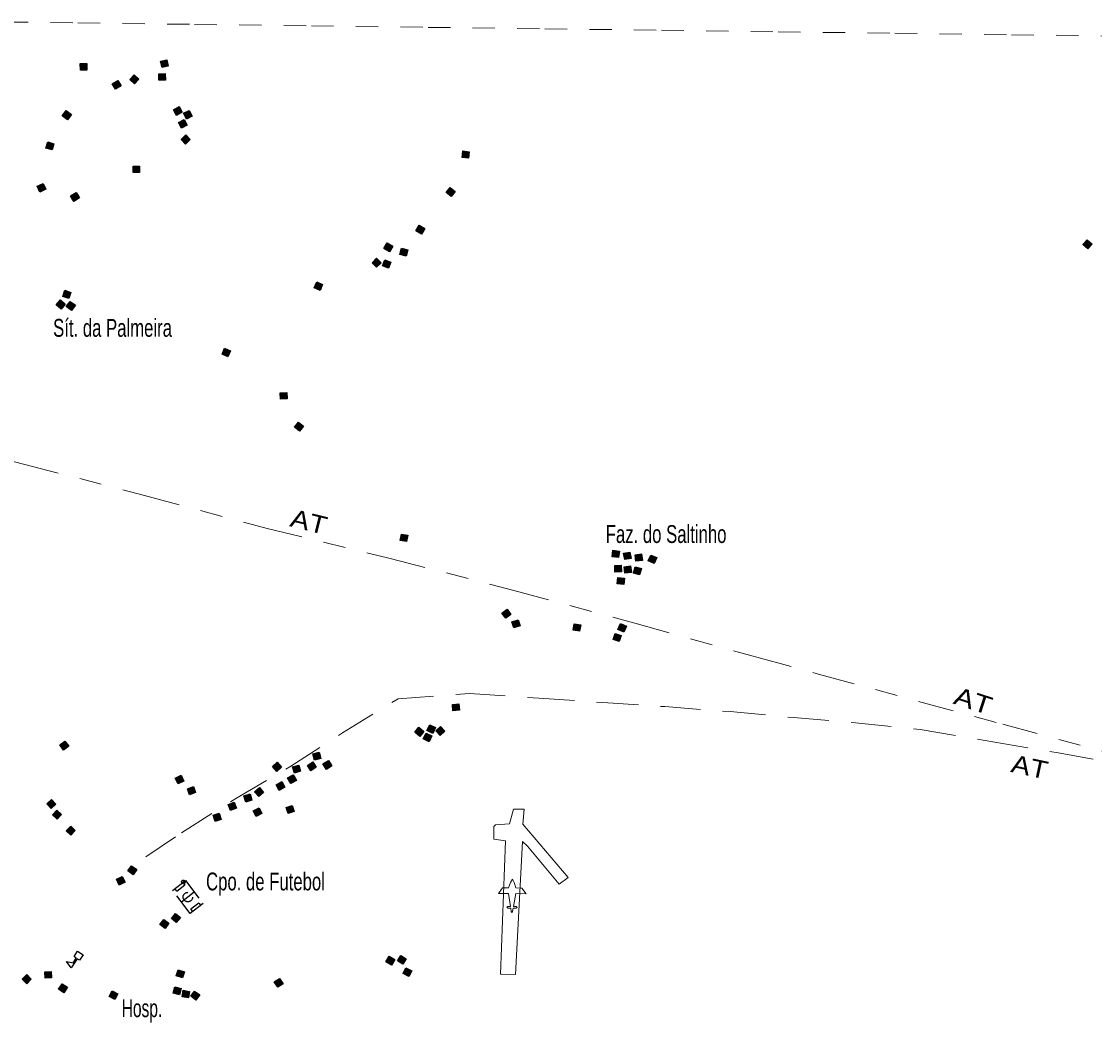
# Model space of a CAD drawing. Extents: x 679 to 705, y 7427.4 to 7455.4.
# Drawn here: x 688.008 to 692.818, y 7450.789 to 7455.274 of the extents above; entities that cross this region are included whole.
import ezdxf
from ezdxf.enums import TextEntityAlignment as Align

# ---------------------------------------------------------------- set-up
doc = ezdxf.new("R2010")
doc.units = 0
doc.header["$LTSCALE"] = 0.032
doc.header["$PDMODE"] = 32
doc.header["$PDSIZE"] = 0.016
for name, pattern in [('DOT_DASHED', [7.7, 5, -1.2, 0.3, -1.2]), ('MEDIUM_DASHED', [4.5, 3, -1.5]), ('SHORT_DASHED', [2.7, 1.5, -1.2])]:
    doc.linetypes.add(name, pattern=pattern)
for name, color, linetype, lineweight in [('14', 7, 'MEDIUM_DASHED', 25), ('18', 7, 'Continuous', 13), ('2', 7, 'Continuous', 25), ('4', 7, 'Continuous', 25), ('56', 7, 'DOT_DASHED', 13), ('58', 7, 'SHORT_DASHED', 13)]:
    doc.layers.add(name, color=color, linetype=linetype, lineweight=lineweight)
doc.layers.add('61', color=7, linetype='Continuous')

msp = doc.modelspace()

# ---------------------------------------------------------------- hatches: boundary and pattern name
at = {"layer": '2'}
for points in [[(688.3013, 7455.0856), (688.3019, 7455.0566), (688.2729, 7455.0561), (688.2723, 7455.0851)], [(688.6602, 7455.1025), (688.6668, 7455.0742), (688.6385, 7455.0677), (688.632, 7455.0959)], [(688.5131, 7455.0352), (688.5347, 7455.0158), (688.5153, 7454.9943), (688.4937, 7455.0137)], [(688.6532, 7455.0403), (688.6537, 7455.0113), (688.6247, 7455.0108), (688.6242, 7455.0398)], [(688.4407, 7455.01), (688.4556, 7454.9852), (688.4307, 7454.9703), (688.4158, 7454.9951)], [(688.7148, 7454.8926), (688.7291, 7454.8674), (688.7038, 7454.8531), (688.6895, 7454.8783)], [(688.2092, 7454.8745), (688.2322, 7454.8568), (688.2145, 7454.8338), (688.1915, 7454.8515)], [(688.7607, 7454.8759), (688.7741, 7454.8502), (688.7484, 7454.8368), (688.735, 7454.8625)], [(688.7379, 7454.8348), (688.7515, 7454.8093), (688.726, 7454.7956), (688.7123, 7454.8211)], [(688.745, 7454.7656), (688.765, 7454.7446), (688.7441, 7454.7246), (688.724, 7454.7455)], [(688.126, 7454.7341), (688.154, 7454.7264), (688.1464, 7454.6984), (688.1184, 7454.7061)], [(690.0152, 7454.6906), (690.0121, 7454.6618), (689.9832, 7454.6649), (689.9864, 7454.6938)], [(688.5382, 7454.6263), (688.5382, 7454.5973), (688.5092, 7454.5973), (688.5092, 7454.6263)], [(688.1052, 7454.5483), (688.1174, 7454.522), (688.0912, 7454.5098), (688.0789, 7454.5361)], [(688.2531, 7454.5078), (688.2685, 7454.4832), (688.2439, 7454.4678), (688.2285, 7454.4924)], [(689.9301, 7454.5307), (689.9526, 7454.5125), (689.9344, 7454.4899), (689.9118, 7454.5082)], [(689.7918, 7454.3614), (689.8165, 7454.3463), (689.8014, 7454.3216), (689.7767, 7454.3367)], [(689.6334, 7454.2569), (689.6477, 7454.2821), (689.6729, 7454.2677), (689.6585, 7454.2426)], [(692.7855, 7454.296), (692.8074, 7454.277), (692.7884, 7454.2551), (692.7665, 7454.2741)], [(689.6003, 7454.2138), (689.6208, 7454.1932), (689.6003, 7454.1727), (689.5798, 7454.1933)], [(689.7114, 7454.258), (689.7397, 7454.2515), (689.7331, 7454.2232), (689.7049, 7454.2298)], [(689.6377, 7454.2058), (689.6648, 7454.1954), (689.6543, 7454.1683), (689.6273, 7454.1787)], [(688.2029, 7454.0697), (688.2302, 7454.0601), (688.2207, 7454.0327), (688.1933, 7454.0423)], [(689.3317, 7454.1072), (689.3584, 7454.096), (689.3472, 7454.0692), (689.3204, 7454.0805)], [(688.1828, 7454.0263), (688.205, 7454.0077), (688.1865, 7453.9855), (688.1642, 7454.004)], [(688.2273, 7454.02), (688.2502, 7454.0023), (688.2326, 7453.9794), (688.2096, 7453.9971)], [(688.9458, 7453.798), (688.9339, 7453.7716), (688.9075, 7453.7834), (688.9193, 7453.8099)], [(689.1977, 7453.6119), (689.1992, 7453.5829), (689.1702, 7453.5815), (689.1688, 7453.6104)], [(689.2504, 7453.4786), (689.2731, 7453.4606), (689.255, 7453.4379), (689.2323, 7453.4559)], [(689.7399, 7452.9719), (689.7344, 7452.9435), (689.7059, 7452.949), (689.7115, 7452.9775)], [(690.6886, 7452.9012), (690.685, 7452.8724), (690.6562, 7452.876), (690.6598, 7452.9048)], [(690.7355, 7452.897), (690.741, 7452.8685), (690.7125, 7452.8631), (690.707, 7452.8916)], [(690.7878, 7452.8882), (690.7918, 7452.8595), (690.763, 7452.8555), (690.7591, 7452.8842)], [(690.856, 7452.8717), (690.8444, 7452.8451), (690.8178, 7452.8567), (690.8294, 7452.8833)], [(690.6966, 7452.8377), (690.6979, 7452.8087), (690.6689, 7452.8074), (690.6676, 7452.8364)], [(690.7385, 7452.8346), (690.7423, 7452.8059), (690.7136, 7452.802), (690.7097, 7452.8308)], [(690.787, 7452.8225), (690.7789, 7452.7946), (690.7511, 7452.8027), (690.7591, 7452.8306)], [(690.7109, 7452.7801), (690.708, 7452.7513), (690.6792, 7452.7541), (690.682, 7452.7829)], [(690.1856, 7452.6404), (690.2026, 7452.6168), (690.1791, 7452.5999), (690.1621, 7452.6234)], [(690.2345, 7452.5933), (690.2435, 7452.5657), (690.216, 7452.5567), (690.207, 7452.5843)], [(690.5152, 7452.5712), (690.5105, 7452.5426), (690.4819, 7452.5473), (690.4866, 7452.5759)], [(690.6968, 7452.5233), (690.6877, 7452.4958), (690.6601, 7452.5049), (690.6693, 7452.5325)], [(690.72, 7452.5653), (690.7089, 7452.5385), (690.6821, 7452.5496), (690.6933, 7452.5764)], [(689.9686, 7452.2164), (689.9713, 7452.1876), (689.9424, 7452.1849), (689.9398, 7452.2138)], [(689.7899, 7452.1115), (689.8121, 7452.0929), (689.7934, 7452.0707), (689.7713, 7452.0894)], [(689.8386, 7452.1228), (689.8648, 7452.1103), (689.8524, 7452.0841), (689.8262, 7452.0966)], [(689.8866, 7452.1158), (689.9067, 7452.0949), (689.8859, 7452.0747), (689.8657, 7452.0956)], [(688.2035, 7452.0497), (688.2206, 7452.0263), (688.1972, 7452.0092), (688.1801, 7452.0326)], [(689.8228, 7452.0859), (689.8485, 7452.0726), (689.8352, 7452.0468), (689.8094, 7452.0602)], [(689.1548, 7451.9552), (689.1742, 7451.9336), (689.1526, 7451.9142), (689.1333, 7451.9358)], [(689.3142, 7451.9569), (689.33, 7451.9325), (689.3056, 7451.9168), (689.2899, 7451.9411)], [(689.343, 7451.9998), (689.3497, 7451.9715), (689.3214, 7451.9649), (689.3148, 7451.9931)], [(689.3843, 7451.963), (689.3999, 7451.9385), (689.3754, 7451.923), (689.3599, 7451.9474)], [(689.2517, 7451.9426), (689.2597, 7451.9147), (689.2318, 7451.9067), (689.2238, 7451.9346)], [(688.7242, 7451.8965), (688.7366, 7451.8703), (688.7104, 7451.8579), (688.698, 7451.8841)], [(689.1756, 7451.868), (689.1897, 7451.8427), (689.1643, 7451.8286), (689.1502, 7451.854)], [(689.2268, 7451.899), (689.2412, 7451.8738), (689.216, 7451.8594), (689.2016, 7451.8846)], [(688.7792, 7451.8465), (688.7893, 7451.8193), (688.7622, 7451.8092), (688.752, 7451.8363)], [(689.0333, 7451.813), (689.0418, 7451.7853), (689.014, 7451.7768), (689.0056, 7451.8046)], [(689.075, 7451.8419), (689.0939, 7451.8199), (689.0719, 7451.801), (689.053, 7451.823)], [(688.1435, 7451.7884), (688.1633, 7451.7672), (688.1422, 7451.7474), (688.1224, 7451.7686)], [(688.9621, 7451.7766), (688.9725, 7451.7495), (688.9455, 7451.7391), (688.9351, 7451.7662)], [(689.222, 7451.7619), (689.2314, 7451.7344), (689.204, 7451.725), (689.1946, 7451.7525)], [(688.1668, 7451.741), (688.1881, 7451.7214), (688.1684, 7451.7001), (688.1471, 7451.7197)], [(688.8952, 7451.7267), (688.9041, 7451.6991), (688.8765, 7451.6902), (688.8676, 7451.7178)], [(689.0733, 7451.7505), (689.0866, 7451.7248), (689.0609, 7451.7114), (689.0475, 7451.7372)], [(688.2291, 7451.669), (688.2498, 7451.6487), (688.2296, 7451.628), (688.2088, 7451.6483)], [(688.5018, 7451.4916), (688.5254, 7451.4748), (688.5087, 7451.4511), (688.485, 7451.4679)], [(688.4601, 7451.4435), (688.4726, 7451.4173), (688.4464, 7451.4049), (688.4339, 7451.431)], [(688.6466, 7451.2508), (688.6697, 7451.2333), (688.6522, 7451.2102), (688.6291, 7451.2277)], [(688.699, 7451.2777), (688.7212, 7451.259), (688.7025, 7451.2368), (688.6803, 7451.2555)], [(689.7087, 7451.0898), (689.7335, 7451.0749), (689.7186, 7451.05), (689.6937, 7451.0649)], [(689.6571, 7451.0856), (689.6821, 7451.0708), (689.6672, 7451.0459), (689.6423, 7451.0607)], [(688.032, 7451.004), (688.0525, 7450.9834), (688.032, 7450.9629), (688.0115, 7450.9835)], [(688.1418, 7451.0176), (688.1432, 7450.9886), (688.1142, 7450.9873), (688.1129, 7451.0163)], [(688.7387, 7451.0162), (688.7296, 7450.9886), (688.702, 7450.9978), (688.7112, 7451.0253)], [(689.732, 7451.0338), (689.7579, 7451.0206), (689.7447, 7450.9948), (689.7189, 7451.008)], [(688.1906, 7450.9623), (688.2149, 7450.9465), (688.199, 7450.9222), (688.1747, 7450.938)], [(688.7238, 7450.9409), (688.7162, 7450.913), (688.6882, 7450.9205), (688.6958, 7450.9485)], [(689.1813, 7450.9624), (689.157, 7450.9465), (689.1411, 7450.9708), (689.1654, 7450.9866)], [(688.4158, 7450.9312), (688.441, 7450.9167), (688.4265, 7450.8916), (688.4014, 7450.906)], [(688.762, 7450.9279), (688.7568, 7450.8994), (688.7282, 7450.9046), (688.7335, 7450.9331)], [(688.7846, 7450.9296), (688.808, 7450.9124), (688.7907, 7450.889), (688.7674, 7450.9063)]]:
    msp.add_hatch(color=256, dxfattribs=at).paths.add_polyline_path(points)

# ---------------------------------------------------------------- linework, layer by layer
at = {"layer": '14'}
for p, q in [((688.7054, 7451.3781), (688.6966, 7451.3894)), ((688.6981, 7451.3905), (688.6976, 7451.3906)), ((688.7054, 7451.3781), (688.7405, 7451.4053)), ((688.7317, 7451.4166), (688.7405, 7451.4053)), ((688.7347, 7451.4189), (688.7347, 7451.4188)), ((688.7831, 7451.3734), (688.7254, 7451.3287)), ((688.8032, 7451.3241), (688.768, 7451.2969)), ((688.7768, 7451.2856), (688.768, 7451.2969)), ((688.8032, 7451.3241), (688.812, 7451.3128))]:
    msp.add_line(p, q, dxfattribs=at)
msp.add_lwpolyline([(688.6853, 7451.3806), (688.7431, 7451.4253), (688.8233, 7451.3215), (688.7654, 7451.2768)], close=True, dxfattribs=at)
msp.add_circle((688.7543, 7451.351), 0.0212, dxfattribs=at)
msp.add_point((688.7344, 7451.4187), dxfattribs=at)
at = {"layer": '18'}
for points in [[(690.2766, 7451.5791), (690.4191, 7451.4084), (690.4583, 7451.4393), (690.2564, 7451.678), (690.2614, 7451.7449), (690.2141, 7451.7455), (690.1964, 7451.6786), (690.1333, 7451.6742), (690.1258, 7451.6672), (690.1251, 7451.6104), (690.1775, 7451.6022), (690.1561, 7451.0055), (690.1584, 7451.0048)], [(690.1584, 7451.0048), (690.2224, 7451.0047), (690.2544, 7451.6003), (690.2766, 7451.5791)]]:
    msp.add_lwpolyline(points, dxfattribs=at)
msp.add_lwpolyline([(690.2088, 7451.4312), (690.2169, 7451.4164), (690.2244, 7451.3916), (690.2517, 7451.3912), (690.2701, 7451.3661), (690.2242, 7451.3666), (690.2145, 7451.3089), (690.2265, 7451.3089), (690.2305, 7451.3046), (690.2264, 7451.3006), (690.2128, 7451.3007), (690.2101, 7451.2865), (690.207, 7451.2823), (690.2039, 7451.2866), (690.2019, 7451.3008), (690.1884, 7451.3009), (690.1842, 7451.3051), (690.1885, 7451.3092), (690.1999, 7451.3092), (690.1919, 7451.3669), (690.146, 7451.3674), (690.1648, 7451.3922), (690.1921, 7451.3919), (690.2002, 7451.4167)], close=True, dxfattribs=at)
at = {"layer": '2'}
for points in [[(688.3013, 7455.0856), (688.3019, 7455.0566), (688.2729, 7455.0561), (688.2723, 7455.0851)], [(688.6602, 7455.1025), (688.6668, 7455.0742), (688.6385, 7455.0677), (688.632, 7455.0959)], [(688.5131, 7455.0352), (688.5347, 7455.0158), (688.5153, 7454.9943), (688.4937, 7455.0137)], [(688.6532, 7455.0403), (688.6537, 7455.0113), (688.6247, 7455.0108), (688.6242, 7455.0398)], [(688.4407, 7455.01), (688.4556, 7454.9852), (688.4307, 7454.9703), (688.4158, 7454.9951)], [(688.7148, 7454.8926), (688.7291, 7454.8674), (688.7038, 7454.8531), (688.6895, 7454.8783)], [(688.2092, 7454.8745), (688.2322, 7454.8568), (688.2145, 7454.8338), (688.1915, 7454.8515)], [(688.7607, 7454.8759), (688.7741, 7454.8502), (688.7484, 7454.8368), (688.735, 7454.8625)], [(688.7379, 7454.8348), (688.7515, 7454.8093), (688.726, 7454.7956), (688.7123, 7454.8211)], [(688.745, 7454.7656), (688.765, 7454.7446), (688.7441, 7454.7246), (688.724, 7454.7455)], [(688.126, 7454.7341), (688.154, 7454.7264), (688.1464, 7454.6984), (688.1184, 7454.7061)], [(690.0152, 7454.6906), (690.0121, 7454.6618), (689.9832, 7454.6649), (689.9864, 7454.6938)], [(688.5382, 7454.6263), (688.5382, 7454.5973), (688.5092, 7454.5973), (688.5092, 7454.6263)], [(688.1052, 7454.5483), (688.1174, 7454.522), (688.0912, 7454.5098), (688.0789, 7454.5361)], [(688.2531, 7454.5078), (688.2685, 7454.4832), (688.2439, 7454.4678), (688.2285, 7454.4924)], [(689.9301, 7454.5307), (689.9526, 7454.5125), (689.9344, 7454.4899), (689.9118, 7454.5082)], [(689.7918, 7454.3614), (689.8165, 7454.3463), (689.8014, 7454.3216), (689.7767, 7454.3367)], [(689.6334, 7454.2569), (689.6477, 7454.2821), (689.6729, 7454.2677), (689.6585, 7454.2426)], [(692.7855, 7454.296), (692.8074, 7454.277), (692.7884, 7454.2551), (692.7665, 7454.2741)], [(689.6003, 7454.2138), (689.6208, 7454.1932), (689.6003, 7454.1727), (689.5798, 7454.1933)], [(689.7114, 7454.258), (689.7397, 7454.2515), (689.7331, 7454.2232), (689.7049, 7454.2298)], [(689.6377, 7454.2058), (689.6648, 7454.1954), (689.6543, 7454.1683), (689.6273, 7454.1787)], [(688.2029, 7454.0697), (688.2302, 7454.0601), (688.2207, 7454.0327), (688.1933, 7454.0423)], [(689.3317, 7454.1072), (689.3584, 7454.096), (689.3472, 7454.0692), (689.3204, 7454.0805)], [(688.1828, 7454.0263), (688.205, 7454.0077), (688.1865, 7453.9855), (688.1642, 7454.004)], [(688.2273, 7454.02), (688.2502, 7454.0023), (688.2326, 7453.9794), (688.2096, 7453.9971)], [(688.9458, 7453.798), (688.9339, 7453.7716), (688.9075, 7453.7834), (688.9193, 7453.8099)], [(689.1977, 7453.6119), (689.1992, 7453.5829), (689.1702, 7453.5815), (689.1688, 7453.6104)], [(689.2504, 7453.4786), (689.2731, 7453.4606), (689.255, 7453.4379), (689.2323, 7453.4559)], [(689.7399, 7452.9719), (689.7344, 7452.9435), (689.7059, 7452.949), (689.7115, 7452.9775)], [(690.6886, 7452.9012), (690.685, 7452.8724), (690.6562, 7452.876), (690.6598, 7452.9048)], [(690.7355, 7452.897), (690.741, 7452.8685), (690.7125, 7452.8631), (690.707, 7452.8916)], [(690.7878, 7452.8882), (690.7918, 7452.8595), (690.763, 7452.8555), (690.7591, 7452.8842)], [(690.856, 7452.8717), (690.8444, 7452.8451), (690.8178, 7452.8567), (690.8294, 7452.8833)], [(690.6966, 7452.8377), (690.6979, 7452.8087), (690.6689, 7452.8074), (690.6676, 7452.8364)], [(690.7385, 7452.8346), (690.7423, 7452.8059), (690.7136, 7452.802), (690.7097, 7452.8308)], [(690.787, 7452.8225), (690.7789, 7452.7946), (690.7511, 7452.8027), (690.7591, 7452.8306)], [(690.7109, 7452.7801), (690.708, 7452.7513), (690.6792, 7452.7541), (690.682, 7452.7829)], [(690.1856, 7452.6404), (690.2026, 7452.6168), (690.1791, 7452.5999), (690.1621, 7452.6234)], [(690.2345, 7452.5933), (690.2435, 7452.5657), (690.216, 7452.5567), (690.207, 7452.5843)], [(690.5152, 7452.5712), (690.5105, 7452.5426), (690.4819, 7452.5473), (690.4866, 7452.5759)], [(690.6968, 7452.5233), (690.6877, 7452.4958), (690.6601, 7452.5049), (690.6693, 7452.5325)], [(690.72, 7452.5653), (690.7089, 7452.5385), (690.6821, 7452.5496), (690.6933, 7452.5764)], [(689.9686, 7452.2164), (689.9713, 7452.1876), (689.9424, 7452.1849), (689.9398, 7452.2138)], [(689.7899, 7452.1115), (689.8121, 7452.0929), (689.7934, 7452.0707), (689.7713, 7452.0894)], [(689.8386, 7452.1228), (689.8648, 7452.1103), (689.8524, 7452.0841), (689.8262, 7452.0966)], [(689.8866, 7452.1158), (689.9067, 7452.0949), (689.8859, 7452.0747), (689.8657, 7452.0956)], [(688.2035, 7452.0497), (688.2206, 7452.0263), (688.1972, 7452.0092), (688.1801, 7452.0326)], [(689.8228, 7452.0859), (689.8485, 7452.0726), (689.8352, 7452.0468), (689.8094, 7452.0602)], [(689.1548, 7451.9552), (689.1742, 7451.9336), (689.1526, 7451.9142), (689.1333, 7451.9358)], [(689.3142, 7451.9569), (689.33, 7451.9325), (689.3056, 7451.9168), (689.2899, 7451.9411)], [(689.343, 7451.9998), (689.3497, 7451.9715), (689.3214, 7451.9649), (689.3148, 7451.9931)], [(689.3843, 7451.963), (689.3999, 7451.9385), (689.3754, 7451.923), (689.3599, 7451.9474)], [(689.2517, 7451.9426), (689.2597, 7451.9147), (689.2318, 7451.9067), (689.2238, 7451.9346)], [(688.7242, 7451.8965), (688.7366, 7451.8703), (688.7104, 7451.8579), (688.698, 7451.8841)], [(689.1756, 7451.868), (689.1897, 7451.8427), (689.1643, 7451.8286), (689.1502, 7451.854)], [(689.2268, 7451.899), (689.2412, 7451.8738), (689.216, 7451.8594), (689.2016, 7451.8846)], [(688.7792, 7451.8465), (688.7893, 7451.8193), (688.7622, 7451.8092), (688.752, 7451.8363)], [(689.0333, 7451.813), (689.0418, 7451.7853), (689.014, 7451.7768), (689.0056, 7451.8046)], [(689.075, 7451.8419), (689.0939, 7451.8199), (689.0719, 7451.801), (689.053, 7451.823)], [(688.1435, 7451.7884), (688.1633, 7451.7672), (688.1422, 7451.7474), (688.1224, 7451.7686)], [(688.9621, 7451.7766), (688.9725, 7451.7495), (688.9455, 7451.7391), (688.9351, 7451.7662)], [(689.222, 7451.7619), (689.2314, 7451.7344), (689.204, 7451.725), (689.1946, 7451.7525)], [(688.1668, 7451.741), (688.1881, 7451.7214), (688.1684, 7451.7001), (688.1471, 7451.7197)], [(688.8952, 7451.7267), (688.9041, 7451.6991), (688.8765, 7451.6902), (688.8676, 7451.7178)], [(689.0733, 7451.7505), (689.0866, 7451.7248), (689.0609, 7451.7114), (689.0475, 7451.7372)], [(688.2291, 7451.669), (688.2498, 7451.6487), (688.2296, 7451.628), (688.2088, 7451.6483)], [(688.5018, 7451.4916), (688.5254, 7451.4748), (688.5087, 7451.4511), (688.485, 7451.4679)], [(688.4601, 7451.4435), (688.4726, 7451.4173), (688.4464, 7451.4049), (688.4339, 7451.431)], [(688.6466, 7451.2508), (688.6697, 7451.2333), (688.6522, 7451.2102), (688.6291, 7451.2277)], [(688.699, 7451.2777), (688.7212, 7451.259), (688.7025, 7451.2368), (688.6803, 7451.2555)], [(689.7087, 7451.0898), (689.7335, 7451.0749), (689.7186, 7451.05), (689.6937, 7451.0649)], [(689.6571, 7451.0856), (689.6821, 7451.0708), (689.6672, 7451.0459), (689.6423, 7451.0607)], [(688.032, 7451.004), (688.0525, 7450.9834), (688.032, 7450.9629), (688.0115, 7450.9835)], [(688.1418, 7451.0176), (688.1432, 7450.9886), (688.1142, 7450.9873), (688.1129, 7451.0163)], [(688.7387, 7451.0162), (688.7296, 7450.9886), (688.702, 7450.9978), (688.7112, 7451.0253)], [(689.732, 7451.0338), (689.7579, 7451.0206), (689.7447, 7450.9948), (689.7189, 7451.008)], [(688.1906, 7450.9623), (688.2149, 7450.9465), (688.199, 7450.9222), (688.1747, 7450.938)], [(688.7238, 7450.9409), (688.7162, 7450.913), (688.6882, 7450.9205), (688.6958, 7450.9485)], [(689.1813, 7450.9624), (689.157, 7450.9465), (689.1411, 7450.9708), (689.1654, 7450.9866)], [(688.4158, 7450.9312), (688.441, 7450.9167), (688.4265, 7450.8916), (688.4014, 7450.906)], [(688.762, 7450.9279), (688.7568, 7450.8994), (688.7282, 7450.9046), (688.7335, 7450.9331)], [(688.7846, 7450.9296), (688.808, 7450.9124), (688.7907, 7450.889), (688.7674, 7450.9063)]]:
    msp.add_lwpolyline(points, close=True, dxfattribs=at)
at = {"layer": '4'}
for points in [[(688.2543, 7451.0773), (688.2442, 7451.084), (688.2603, 7451.1082), (688.2845, 7451.0921), (688.2684, 7451.0679), (688.2584, 7451.0746)], [(688.2584, 7451.0746), (688.2315, 7451.0343), (688.2098, 7451.0628), (688.2398, 7451.0556), (688.2543, 7451.0773)]]:
    msp.add_lwpolyline(points, dxfattribs=at)
at = {"layer": '56'}
for points in [[(685.0003, 7453.9163), (685.013, 7453.9116), (685.2285, 7453.8725), (685.5082, 7453.8208), (686.0678, 7453.7211), (686.3459, 7453.6633), (686.9027, 7453.5508), (687.4611, 7453.431), (688.0181, 7453.2912), (688.5601, 7453.1499), (689.1094, 7453.0028), (689.6616, 7452.8679), (690.2157, 7452.7249), (690.7571, 7452.5778), (691.3047, 7452.426), (691.5859, 7452.3484), (692.4067, 7452.1254), (693.1904, 7451.9134), (693.214, 7451.907)], [(688.5663, 7451.5305), (688.7265, 7451.6388), (688.9692, 7451.7931), (689.2108, 7451.9345), (689.4472, 7452.0863), (689.6965, 7452.2391), (690.0165, 7452.2624), (690.3273, 7452.2423), (690.6141, 7452.2221), (690.8921, 7452.2041), (691.1848, 7452.1818), (691.4685, 7452.1552), (691.7475, 7452.1319), (692.0371, 7452.1022), (692.3622, 7452.0468), (692.6549, 7451.9969), (692.9176, 7451.9512), (693.1955, 7451.9095), (693.214, 7451.907)]]:
    msp.add_lwpolyline(points, dxfattribs=at)
at = {"layer": '58'}
msp.add_lwpolyline([(687.7386, 7455.2741), (688.2617, 7455.2676), (688.7848, 7455.261), (689.3078, 7455.2544), (689.8309, 7455.2478), (690.354, 7455.2412), (690.8771, 7455.2346), (691.4002, 7455.2279), (691.9232, 7455.2213), (692.4463, 7455.2146), (692.9694, 7455.2079), (693.4925, 7455.2011), (694.0156, 7455.1944), (694.5387, 7455.1876), (695.0618, 7455.1808), (695.5848, 7455.174), (696.1079, 7455.1672), (696.631, 7455.1604), (697.1541, 7455.1535), (697.6772, 7455.1467)], dxfattribs=at)

# ---------------------------------------------------------------- texts
at = {"layer": '61'}
for s, width, p in [('Sít. da Palmeira', 0.7, (688.1504, 7453.8613)), ('Faz. do Saltinho', 0.7, (690.6274, 7452.9375)), ('Cpo. de Futebol', 0.7, (688.8359, 7451.3808)), ('Hosp.', 0.65, (688.458, 7450.8129))]:
    msp.add_text(s, height=0.08, dxfattribs=dict(at, width=width)).set_placement(p)
for rotation, width, p in [(346.222, 1.2, (689.2871, 7452.9935)), (342.102, 1.25, (692.2621, 7452.1922)), (347.898, 1.2, (692.5192, 7451.8949))]:
    msp.add_text('AT', height=0.08, rotation=rotation, dxfattribs=dict(at, width=width)).set_placement(p, align=Align.CENTER)

doc.saveas('drawing.dxf')
